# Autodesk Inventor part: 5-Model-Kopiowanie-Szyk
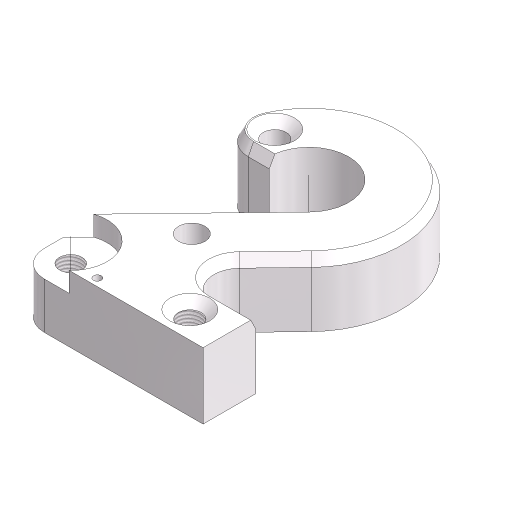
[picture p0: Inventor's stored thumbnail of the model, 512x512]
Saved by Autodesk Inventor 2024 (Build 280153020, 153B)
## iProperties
Company: ATC
Shininess: 21.0
Length Units: 11269
Angle Units: 11279
Time Units: 11290
Mass Units: 11283
Compacted: True
Created: 2023-03
Part Number: 5-Model-Kopiowanie-Szyk
Document SubType Name: Modeling
Designer: Andrzej Jaskulski
Material: Kurs-AJ
Density: 1 g/cm^3
Appearance: Kurs-AJ
Mass: 803.818 g
Surface Area: 871.092 cm^2
Volume: 803.818 cm^3
Checked By: A.J.
Engr Approved By: Andrzej Jaskulski
Mfg Approved By: Andrzej Jaskulski
Authority: A.J.
Density: 0.0
Volumn: 0.0
Area: 0.0
PropertySet Name: Model Information
Control State: 0
Master: False
Checked Out: False
Title: A.J.: Kurs R2024-MEP
Author: Andrzej Jaskulski
Revision Number: 1/24
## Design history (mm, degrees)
sketch "Zarys dwójki"
  geometry: L1 (140, 0.063)-(0, 0.063) reference; L2 (0, 0.063)-(0, 34.389) reference; L3 (0, 150.063)-(40, 150.063); L4 (140, 0.063)-(140, 40.063); L5 (140, 40.063)-(61.086, 40.063); L6 (61.086, 40.063)-(120.354, 101.437); L7 (91.58, 129.223)-(0, 34.389); A1 r 30 centre (70, 150.063) between (91.58, 129.223) and (40, 150.063); A2 r 70 centre (70, 150.063) between (120.354, 101.437) and (0, 150.063)
  constraints: 14 end point, 4 perpendicular, 4 point on circle, 2 centre point, 2 parallel, 2 tangent, 1 coincident
  dimensions: "d0" = 140 distance of L1.start L1.end; "d1" = 150 vertical distance of A1.centre L1.end; "d2" = 70 horizontal distance of L1.end A1.centre; "d3" = 46 deg angle of L6 L5; "d4" = 150 distance of L3.start L1.end (= d1); "d5" = 30 radius of A1; "d6" = 70 radius of A2
extrude "Dwójka" new body sketch "Zarys dwójki" distance "d7" = 50; taper "d8" = 0 deg
node "Oś walca"
fillet "Fillet1" dims "d12" = 20
chamfer "Chamfer1" distance "d13" = 4; stored, may be unused: second distance "d14" = 8, angle "d68" = 45 deg
sketch "Otwór1"
  geometry: A1 r 20 centre (20, 20.063) between (0, 20.063) and (20, 0.063) reference
hole "Hole1" sketch "Otwór1" at (20, 20.063) diameter "d15" = 17; stored, may be unused: countersink angle "d19" = 60 deg, drill point angle "d21" = 118 deg; dims "d16" = 42, "d17" = 55, "d18" = 15, "d20" = 45
node "Oś Hole1"
sketch "Otwór2"
  geometry: L1 (140, 0.063)-(38.875, 0.063) reference; L2 (140, 36.063)-(140, 0.063) reference; 1 further point
  dimensions: "d24" = 20 distance from line of point (110, 20.063) L1; "d25" = 30 distance from line of L2 point (110, 20.063)
hole "Hole2" sketch "Otwór2" at (110, 20.063) diameter "d26" = 17.4; stored, may be unused: countersink angle "d30" = 90 deg, drill point angle "d32" = 118 deg; dims "d27" = 12, "d28" = 30, "d29" = 15, "d31" = 45
sketch "Szkic3"
  geometry: L1 (11.385, 46.179)-(91.58, 129.223) reference; L2 (61.221, 70.32)-(25.575, 33.408); C1 r 15 at (110, 20.063) reference; A1 r 27.5 centre (20, 20.063) between (38.875, 0.063) and (11.385, 46.179) reference
  constraints: 2 end point, 1 parallel
  dimensions: "d33" = 70 distance from line of L2 C1.centre; "d34" = 65 distance of L2.start A1.centre
hole "Hole3" sketch "Szkic3" at (61.221, 70.32) diameter "d35" = 20; stored, may be unused: countersink angle "d39" = 60 deg, drill point angle "d41" = 118 deg; dims "d36" = 12, "d37" = 30, "d38" = 15, "d40" = 45
thread "Thread1" dims "d42" = 10, "d43" = 0
sketch "Oś otworu"
  geometry: A1 r 16 centre (85.597, -3.545) between (70.932, 2.855) and (85.597, -19.545) reference; 1 further point
  constraints: 1 coincident
hole "Oryginał" sketch "Oś otworu" at (85.597, -3.545) diameter "d61" = 17.4 (= d26); stored, may be unused: drill point angle "d56" = 118 deg, countersink angle "d57" = 90 deg (= d30); dims "d53" = 12 (= d27), "d58" = 15, "d59" = 30 (= d28), "d60" = 45
sketch "Sketch7"
  geometry: 1 further point
hole "Oryginał mały" sketch "Sketch7" at (55.087, 10.632) diameter "d67" = 6; stored, may be unused: drill point angle "d62" = 90 deg, countersink angle "d63" = 60 deg; dims "d64" = 2, "d65" = 30, "d66" = 8
node "Bryła1"
node "Korpusy bryłowe"
node "Korpusy powierzchniowe"
other parameters: "d9" = 90 deg
